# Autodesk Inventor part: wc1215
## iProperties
Shininess: 64.0
Length Units: 11272
Angle Units: 11279
Time Units: 11290
Mass Units: 11286
Length Display Precision: 3
Angle Display Precision: 2
Compacted: True
Part Number: wc1215
Document SubType Name: Modeling
Created: 2004-08
Designer: John Blackburn
Manufacturer: Standard
Standards Organization: Custom
Material: Aluminum-6061
Density: 0.0
Volumn: 0.0
Area: 0.0
PropertySet Name: Model Information
Control State: 0
Master: False
Checked Out: False
Author: John Blackburn
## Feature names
1. Base1
